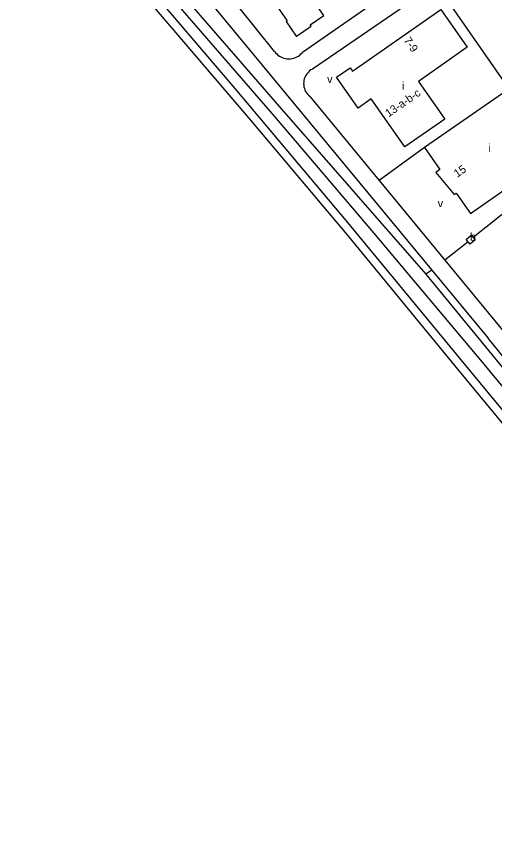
# Model space of a CAD drawing. Extents: x 156721 to 158827, y 386657 to 388950.
# Drawn here: x 156961.7 to 157200.4, y 387580.5 to 387994 of the extents above; entities that cross this region are included whole.
import ezdxf

# ---------------------------------------------------------------- set-up
doc = ezdxf.new("R2010")
doc.units = 0
for name, color, linetype in [('BLT_Basislijn', 7, 'Continuous'), ('BLT_Bebouwing', 7, 'Continuous'), ('BLT_Centroide', 7, 'Continuous'), ('BLT_Huisnummer', 7, 'Continuous'), ('BLT_Huisnummer_reeks', 7, 'Continuous'), ('BLT_Spoorlijn', 7, 'Continuous'), ('BLT_Vlakafsluiter', 7, 'Continuous')]:
    doc.layers.add(name, color=color, linetype=linetype)

msp = doc.modelspace()

# ---------------------------------------------------------------- linework, layer by layer
at = {"layer": 'BLT_Basislijn'}
for p, q in [((157036.15, 388028.01), (157169.06, 387867.32)), ((157171.21, 388010.02), (157109.44, 387967.74)), ((157104.5, 387976.17), (157143.6, 388003.53)), ((157090.57, 387976.6), (157072.83, 387998.56)), ((157108.42, 387953.95), (157142.84, 387912.13)), ((157165.54, 387928.55), (157142.84, 387912.13)), ((157233.44, 387918.44), (157189.79, 387883.58)), ((157142.84, 387912.13), (157175.64, 387872.29)), ((157187.22, 387881.53), (157175.64, 387872.29)), ((157175.64, 387872.29), (157207.57, 387833.5)), ((157169.06, 387867.32), (157197.22, 387833.28)), ((157256.41, 387760.38), (157197.22, 387833.28))]:
    msp.add_line(p, q, dxfattribs=at)
for points in [[(156975.19, 388084.73), (157094.16, 387947.52), (157166.18, 387865.29)], [(157090.57, 387976.6), (157091.08, 387975.94), (157091.65, 387975.34), (157092.28, 387974.79), (157092.96, 387974.3), (157093.68, 387973.88), (157094.44, 387973.54), (157095.23, 387973.26), (157096.05, 387973.07), (157096.87, 387972.95), (157097.71, 387972.91), (157098.54, 387972.95), (157099.37, 387973.07), (157100.18, 387973.27), (157100.97, 387973.54), (157101.73, 387973.89), (157102.45, 387974.31), (157103.12, 387974.8), (157103.75, 387975.35), (157104.33, 387975.96), (157104.5, 387976.17)], [(157109.44, 387967.74), (157108.75, 387967.33), (157108.1, 387966.85), (157107.5, 387966.31), (157106.95, 387965.72), (157106.47, 387965.07), (157106.05, 387964.38), (157105.71, 387963.65), (157105.43, 387962.89), (157105.24, 387962.11), (157105.12, 387961.31), (157105.08, 387960.5), (157105.12, 387959.7), (157105.25, 387958.9), (157105.45, 387958.12), (157105.72, 387957.36), (157106.07, 387956.63), (157106.49, 387955.94), (157106.98, 387955.3), (157107.53, 387954.7), (157108.13, 387954.17), (157108.42, 387953.95)], [(157166.18, 387865.29), (157399.27, 387581.46), (157404.73, 387580.46)]]:
    msp.add_lwpolyline(points, dxfattribs=at)
at = {"layer": 'BLT_Bebouwing'}
for points in [[(157092.39, 388012.46), (157094.11, 388009.99), (157087.55, 388005.42), (157096.89, 387991.93), (157096.38, 387991.5), (157101.36, 387984.23), (157101.56, 387984.19), (157108.81, 387989.27), (157108.4, 387989.85), (157115.14, 387994.59), (157112.1, 387998.97), (157119.01, 388003.77), (157115.85, 388008.3)], [(157207.74, 387957.97), (157179.18, 387998.98), (157178.48, 388000), (157177.3, 388001.69)], [(157206.52, 387957.11), (157165.48, 387928.64), (157165.54, 387928.55)], [(157165.54, 387928.55), (157173.14, 387917.58), (157171.09, 387916.15), (157180.33, 387905.07), (157181.34, 387905.77), (157188.39, 387895.62)], [(157188.39, 387895.62), (157229.38, 387924.28)], [(157187.22, 387881.53), (157186.3, 387882.65), (157188.84, 387884.75), (157189.79, 387883.58)], [(157189.79, 387883.58), (157190.73, 387882.42), (157188.22, 387880.33), (157187.22, 387881.53)]]:
    msp.add_lwpolyline(points, dxfattribs=at)
msp.add_lwpolyline([(157173.58, 387997.58), (157186.78, 387978.67), (157162.4, 387961.64), (157175.57, 387942.78), (157155.62, 387928.88), (157138.87, 387952.87), (157132.32, 387948.3), (157121.58, 387963.7), (157128.3, 387968.4), (157129.48, 387966.8)], close=True, dxfattribs=at)
at = {"layer": 'BLT_Spoorlijn'}
for points in [[(156965.23, 388081.75), (157070.65, 387958.09)], [(156971.42, 388081.45), (157090.38, 387944.24)], [(156961.7, 388079.1), (157078.6, 387942.18)], [(157070.65, 387958.09), (157126.99, 387891.18)], [(157090.38, 387944.24), (157139.96, 387886.02)], [(157078.6, 387942.18), (157126.7, 387885.14)], [(157126.99, 387891.18), (157186.72, 387818.75)], [(157139.96, 387886.02), (157195.18, 387820.31)], [(157126.7, 387885.14), (157182.81, 387816.87)], [(157195.18, 387820.31), (157259.34, 387742.67)], [(157182.81, 387816.87), (157248.7, 387737.07)], [(157186.72, 387818.75), (157252.61, 387739.06)]]:
    msp.add_lwpolyline(points, dxfattribs=at)
at = {"layer": 'BLT_Vlakafsluiter'}
msp.add_line((157169.06, 387867.32), (157166.18, 387865.29), dxfattribs=at)

# ---------------------------------------------------------------- texts
at = {"layer": 'BLT_Centroide'}
for s, p in [('v', (157116.85, 387960.76)), ('i', (157154.19, 387957.48)), ('i', (157197.43, 387926.41)), ('v', (157172.08, 387898.8)), ('b', (157188.15, 387882.03))]:
    msp.add_text(s, height=4, dxfattribs=at).set_placement(p)
at = {"layer": 'BLT_Huisnummer'}
msp.add_text('15', height=4, rotation=34.8412, dxfattribs=at).set_placement((157181.84, 387913.46))
at = {"layer": 'BLT_Huisnummer_reeks'}
for s, rotation, p in [('7-9', 304.9208, (157154.87, 387982.1)), ('13-a-b-c', 34.8715, (157147.56, 387943.6))]:
    msp.add_text(s, height=4, rotation=rotation, dxfattribs=at).set_placement(p)

doc.saveas('drawing.dxf')
